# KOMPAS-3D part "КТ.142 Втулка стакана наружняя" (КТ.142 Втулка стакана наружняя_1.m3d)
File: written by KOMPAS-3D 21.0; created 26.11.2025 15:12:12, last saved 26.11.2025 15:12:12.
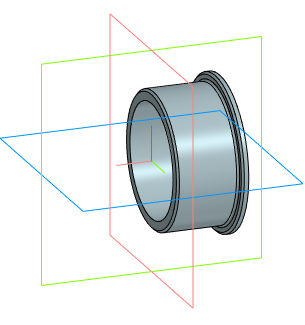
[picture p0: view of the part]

Document properties: Автор: User; Организация: User; Полное имя файла: C:\Users\User\Desktop\Pelorus PRO доработки\ЗАФИКСИРОВАЛИ\Втулка стакана наружняя\КТ.142 Втулка стакана наружняя_1.m3d

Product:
- Part/product: КТ.142 Втулка стакана наружняя
    Комментарий: User

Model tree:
1. Операция без истории:1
